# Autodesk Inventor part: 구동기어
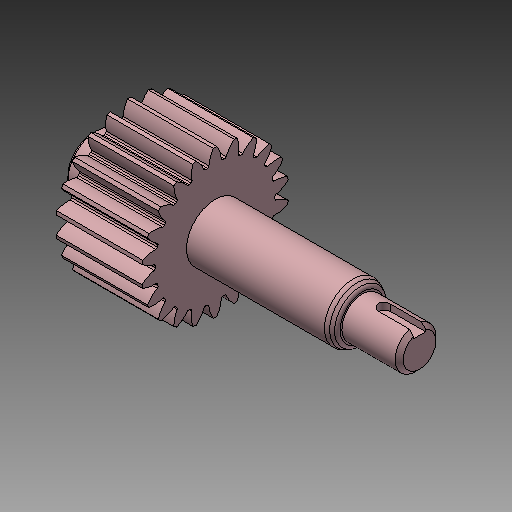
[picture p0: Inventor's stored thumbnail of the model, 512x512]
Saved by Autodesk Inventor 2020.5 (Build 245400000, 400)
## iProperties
Created: 2024-02
Part Number: 구동기어
Material: 강철, 탄소
Document SubType Name: Modeling
Designer: mdu-01
Density: 1 g/cm^3
Appearance: 기본값(1)
Author: mdu-01
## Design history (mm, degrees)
sketch "스케치1"
  geometry: L1 (0, 0)-(80, 0); L2 (80, 0)-(80, 4); L3 (79, 5)-(66, 5); L4 (66, 5)-(66, 5.423); L5 (63.732, 7)-(30, 7); L6 (30, 7)-(30, 14.625); L7 (30, 14.625)-(9, 14.625); L8 (9, 14.625)-(9, 7); L9 (9, 7)-(1, 7); L10 (0, 6)-(0, 0); L11 (9, 16.5)-(30, 16.5); L12 (80, 4)-(79, 5); L13 (1, 7)-(0, 6); L14 (65.5, 6.289)-(64.732, 6.732); L15 (70, 5)-(70, 3.2); L16 (70, 3.2)-(80, 3.2); A1 r 2 centre (63.732, 5) between (64.732, 6.732) and (63.732, 7); A2 r 1 centre (65, 5.423) between (66, 5.423) and (65.5, 6.289); 3 further points
  constraints: 32 end point, 10 point on line, 8 parallel, 4 perpendicular, 4 point on circle, 4 tangent, 2 centre point, 1 collinear, 1 horizontal
  dimensions: "d0" = 14 diameter of L9 L1; "d2" = 9 distance between parallel lines of L8 L10; "d3" = 21 distance between parallel lines of L6 L8; "d4" = 33 diameter of L11 L1; "d5" = 1.875 distance between parallel lines of L7 L11; "d6" = 14 distance between parallel lines of L2 L4; "d7" = 50 distance between parallel lines of L6 L2; "d8" = 10 diameter of L3 L1; "d9" = 1 distance of L2.end point (80, 5); "d10" = 1 distance of L3.start point (80, 5) (= d9); "d11" = 1 distance of L9.end point (0, 7) (= d9); "d12" = 1 distance of L10.start point (0, 7) (= d11); "d13" = 12 diameter of point (66, 6) L1; "d14" = 30 deg angle of L5 L14; "d15" = 2 radius of A1; "d16" = 1 radius of A2; "d17" = 1.8 distance between parallel lines of L16 L3; "d18" = 10 distance between parallel lines of L15 L2
revolve "회전1" stored, may be unused: angle "d19" = 90 deg
extrude "돌출1" cut sketch "스케치1" stored distance "d20" = 3; taper "d21" = 0 deg
fillet "모깎기1"
sketch "스케치2" dims "d22" = 33
  geometry: L1 (0, 0)-(0, 18); A1 r 18 centre (0, 0) between (0.428, 17.995) and (-0.428, 17.995); A2 r 7.045 centre (-5.482, 14.16) between (1.553, 14.542) and (0.428, 17.995); A3 r 7.045 centre (5.482, 14.16) between (-0.428, 17.995) and (-1.553, 14.542); A4 r 14.625 centre (0, 0) between (1.553, 14.542) and (-1.553, 14.542); 3 further points
  constraints: 10 point on circle, 4 centre point, 3 symmetric about line, 2 coincident, 2 end point, 1 vertical, 8 other
  dimensions: "d23" = 1.5 dimension on A1; "d24" = 1.1775 horizontal distance of point (1.178, 16.458) point (0, 0); "d25" = 0.75 horizontal distance of A1.start point (1.178, 16.458); "d26" = 0.375 horizontal distance of A2.start point (1.178, 16.458)
extrude "돌출2" join sketch "스케치2" stored distance "d27" = 3; taper "d28" = 0 deg
fillet "모깎기2" dims "d32" = 0.375
node "솔리드1"
pattern_circular "원형 패턴1" dims angle "d34" = 360 deg
